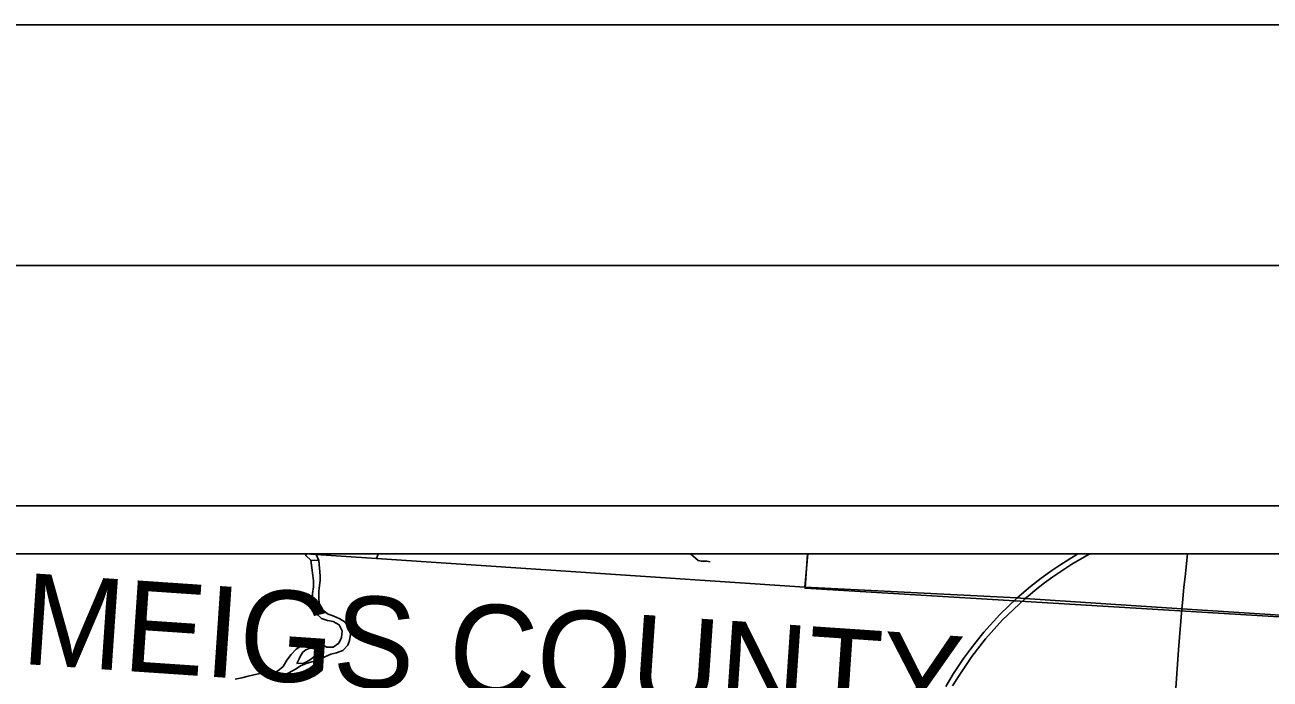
# Model space of a CAD drawing. Extents: x 0 to 34, y 0 to 22.
# Drawn here: x 4.807 to 7.394, y 20.64 to 22 of the extents above; entities that cross this region are included whole.
import ezdxf

# ---------------------------------------------------------------- set-up
doc = ezdxf.new("R2010")
doc.units = 0
for name, color, linetype in [('GM_X_Corporation', 7, 'Continuous'), ('GM_X_County_Text', 7, 'Continuous'), ('GM_X_Major_River', 7, 'Continuous'), ('GM_X_State_Route', 7, 'Continuous'), ('GM_X_Township_Road', 7, 'Continuous'), ('GM_X_Township_Text', 7, 'Continuous'), ('SH_Border', 7, 'Continuous'), ('SH_Cut_Line', 7, 'Continuous'), ('SH_Data', 7, 'Continuous')]:
    doc.layers.add(name, color=color, linetype=linetype)

msp = doc.modelspace()

# ---------------------------------------------------------------- linework, layer by layer
at = {"layer": 'GM_X_Corporation'}
for points in [[(6.4339, 20.9), (5.3907, 20.9), (5.5376, 20.8903), (6.4275, 20.8307)], [(6.4339, 20.9), (5.3907, 20.9), (5.5376, 20.8903), (6.4275, 20.8307)], [(8.9, 20.6767), (8.9, 20.9), (6.4339, 20.9), (6.4275, 20.8307), (6.8677, 20.8085), (6.8847, 20.8074), (7.2108, 20.7862), (7.9767, 20.7364), (8.6343, 20.694)], [(8.9, 20.6767), (8.9, 20.9), (6.4339, 20.9), (6.4275, 20.8307), (6.8677, 20.8085), (6.8847, 20.8074), (7.2108, 20.7862), (7.9767, 20.7364), (8.6343, 20.694)], [(7.4684, 20.9), (6.4334, 20.9), (6.4281, 20.8286), (7.4587, 20.7663)]]:
    msp.add_lwpolyline(points, close=True, dxfattribs=at)
at = {"layer": 'GM_X_Major_River'}
for q in [(5.4009, 20.8873), (5.4117, 20.9)]:
    msp.add_line((5.4177, 20.8862), q, dxfattribs=at)
for points in [[(5.4009, 20.8873), (5.4054, 20.8553), (5.4066, 20.8443), (5.4066, 20.8318), (5.4047, 20.8178), (5.4044, 20.8038), (5.4056, 20.7901), (5.4117, 20.7772), (5.4234, 20.7655), (5.4355, 20.7618), (5.4473, 20.7595), (5.4598, 20.7527), (5.4659, 20.7399), (5.4648, 20.7266), (5.4591, 20.7148), (5.4478, 20.7061), (5.4341, 20.7064), (5.4228, 20.7124), (5.4095, 20.7162), (5.3963, 20.7161), (5.3845, 20.7112), (5.3709, 20.7024), (5.36, 20.691), (5.3513, 20.6792), (5.3438, 20.6663), (5.3317, 20.6561), (5.3192, 20.6534), (5.3056, 20.6514), (5.2927, 20.6506), (5.2829, 20.6487), (5.2711, 20.6457), (5.2579, 20.6426), (5.2439, 20.6395)], [(5.3891, 20.9), (5.3917, 20.8959), (5.4009, 20.8873)], [(5.4202, 20.8548), (5.4177, 20.8862)], [(5.3169, 20.639), (5.3294, 20.6432), (5.3438, 20.6474), (5.3555, 20.6527), (5.3691, 20.6603), (5.3812, 20.6683), (5.3937, 20.6733), (5.4058, 20.6767), (5.4172, 20.6806), (5.43, 20.6859), (5.4425, 20.692), (5.4546, 20.6943), (5.4675, 20.6993), (5.478, 20.7107), (5.4818, 20.7202), (5.4837, 20.7335), (5.481, 20.746), (5.4726, 20.7581), (5.4613, 20.7652), (5.4488, 20.7709), (5.4355, 20.7758), (5.4241, 20.7849), (5.4184, 20.797), (5.4176, 20.8095), (5.418, 20.8228), (5.4191, 20.8345), (5.4202, 20.8451), (5.4202, 20.8548)], [(5.4262, 20.6973), (5.4194, 20.6995), (5.4111, 20.7022), (5.4035, 20.704), (5.3974, 20.7036), (5.391, 20.701), (5.3846, 20.696), (5.3797, 20.6884), (5.3767, 20.6823), (5.3721, 20.6721)], [(5.3721, 20.6721), (5.3865, 20.6733), (5.3933, 20.6767), (5.4001, 20.6805), (5.4066, 20.6855), (5.4126, 20.6881), (5.4171, 20.6904), (5.4221, 20.6927), (5.4262, 20.6973)]]:
    msp.add_lwpolyline(points, dxfattribs=at)
at = {"layer": 'GM_X_State_Route'}
for points in [[(6.8679, 20.8079), (6.8775, 20.8161), (6.8964, 20.8322), (6.9187, 20.8496), (6.9408, 20.8657), (6.9575, 20.877), (6.9784, 20.8902), (6.9903, 20.8975), (6.9948, 20.9)], [(6.8849, 20.8068), (6.8956, 20.816), (6.9062, 20.8247), (6.9258, 20.8401), (6.9428, 20.8526), (6.9613, 20.8652), (6.9823, 20.8786), (7.0037, 20.8913), (7.0195, 20.9)], [(7.211, 20.7857), (7.2121, 20.7981), (7.2152, 20.8312), (7.2175, 20.8523), (7.2227, 20.9)], [(6.7204, 20.6247), (6.7367, 20.6518), (6.7569, 20.6824), (6.7718, 20.7019), (6.7834, 20.7174), (6.7998, 20.7375), (6.8327, 20.7741), (6.8679, 20.8079)], [(6.7343, 20.6255), (6.7479, 20.6473), (6.7746, 20.6869), (6.8032, 20.7235), (6.8381, 20.7629), (6.8849, 20.8068)], [(6.8765, 20.1348), (6.8917, 20.1563), (6.9187, 20.1927), (6.9454, 20.2299), (6.972, 20.264), (6.9879, 20.2817), (6.9976, 20.2919), (7.0749, 20.3652), (7.1375, 20.4273), (7.1647, 20.4515), (7.1775, 20.4643), (7.1829, 20.4732), (7.1873, 20.4837), (7.1902, 20.4999), (7.1949, 20.5711), (7.2038, 20.701), (7.211, 20.7857)]]:
    msp.add_lwpolyline(points, dxfattribs=at)
at = {"layer": 'GM_X_Township_Road'}
msp.add_line((5.5378, 20.8898), (5.5411, 20.9), dxfattribs=at)
msp.add_lwpolyline([(6.1902, 20.9), (6.206, 20.8863), (6.2127, 20.8847), (6.2238, 20.8848), (6.2308, 20.8835)], dxfattribs=at)
at = {"layer": 'GM_X_Township_Text'}
msp.add_lwpolyline([(8.9, 20.6767), (8.6343, 20.694), (7.9767, 20.7364), (7.2108, 20.7862), (6.8847, 20.8074), (6.8677, 20.8085), (6.4275, 20.8307), (5.5376, 20.8903), (5.3907, 20.9)], dxfattribs=at)
at = {"layer": 'SH_Border'}
msp.add_lwpolyline([(1.5, 21.5), (33.5, 21.5), (33.5, 0.5), (1.5, 0.5)], close=True, dxfattribs=at)
at = {"layer": 'SH_Cut_Line'}
msp.add_lwpolyline([(0, 0), (34, 0), (34, 22), (0, 22)], close=True, dxfattribs=at)
at = {"layer": 'SH_Data'}
for p, q in [((2, 21), (9, 21)), ((2.1, 20.9), (8.9, 20.9))]:
    msp.add_line(p, q, dxfattribs=at)

# ---------------------------------------------------------------- texts
at = {"layer": 'GM_X_County_Text'}
msp.add_text('MEIGS COUNTY', height=0.189394, rotation=356.1113, dxfattribs=at).set_placement((4.7976, 20.6717))

doc.saveas('drawing.dxf')
